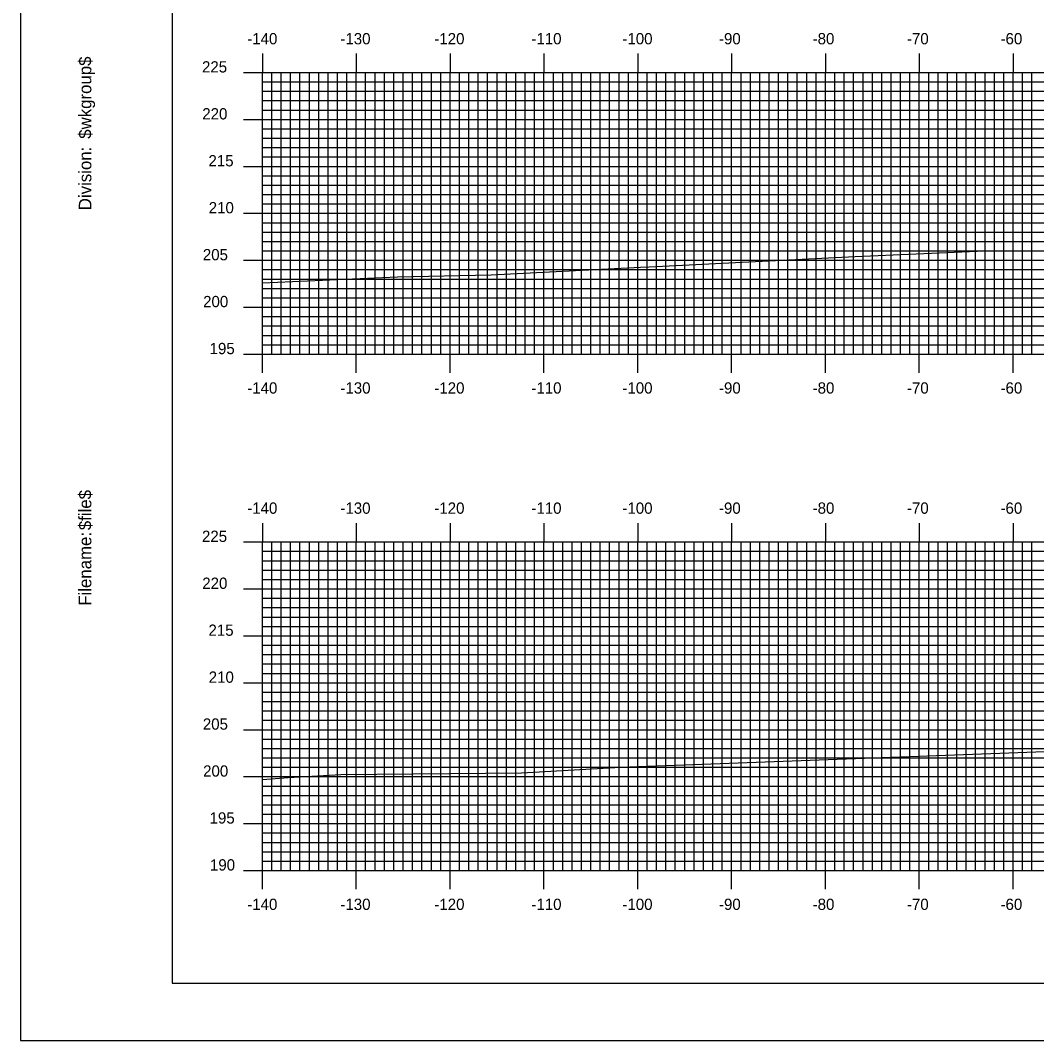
# Model space of a CAD drawing. Extents: x 853316 to 853659, y 364785 to 365005.
# Drawn here: x 853316 to 853424.3, y 364785.1 to 364893.8 of the extents above; entities that cross this region are included whole.
import ezdxf

# ---------------------------------------------------------------- set-up
doc = ezdxf.new("R2010")
doc.units = 0
for name, color, linetype in [('BORDER', 7, 'Continuous'), ('H_V ANNOTATION', 7, 'Continuous'), ('MAJOR', 7, 'Continuous'), ('MINOR', 7, 'Continuous'), ('PLOT BOUNDARY', 7, 'Continuous'), ('S_Roadway_Centerline', 7, 'Continuous')]:
    doc.layers.add(name, color=color, linetype=linetype)

msp = doc.modelspace()

# ---------------------------------------------------------------- linework, layer by layer
at = {"layer": 'BORDER'}
msp.add_lwpolyline([(853332.16, 364791.23), (853652.16, 364791.23), (853652.16, 365001.23), (853332.16, 365001.23)], close=True, dxfattribs=at)
at = {"layer": 'MAJOR'}
for p, q in [((853341.76, 364890.24), (853341.76, 364888.23)), ((853351.76, 364890.24), (853351.76, 364888.23)), ((853361.76, 364890.24), (853361.76, 364888.23)), ((853371.76, 364890.24), (853371.76, 364888.23)), ((853381.76, 364890.24), (853381.76, 364888.23)), ((853391.76, 364890.24), (853391.76, 364888.23)), ((853401.76, 364890.24), (853401.76, 364888.23)), ((853411.76, 364890.24), (853411.76, 364888.23)), ((853421.76, 364890.24), (853421.76, 364888.23)), ((853339.75, 364888.23), (853341.76, 364888.23)), ((853341.76, 364888.23), (853621.76, 364888.23)), ((853341.76, 364858.23), (853341.76, 364888.23)), ((853341.76, 364858.23), (853341.76, 364888.23)), ((853341.76, 364888.23), (853621.76, 364888.23)), ((853351.76, 364858.23), (853351.76, 364888.23)), ((853361.76, 364858.23), (853361.76, 364888.23)), ((853371.76, 364858.23), (853371.76, 364888.23)), ((853381.76, 364858.23), (853381.76, 364888.23)), ((853391.76, 364858.23), (853391.76, 364888.23)), ((853401.76, 364858.23), (853401.76, 364888.23)), ((853411.76, 364858.23), (853411.76, 364888.23)), ((853421.76, 364858.23), (853421.76, 364888.23)), ((853339.75, 364883.23), (853341.76, 364883.23)), ((853341.76, 364883.23), (853621.76, 364883.23)), ((853339.75, 364878.23), (853341.76, 364878.23)), ((853341.76, 364878.23), (853621.76, 364878.23)), ((853339.75, 364873.23), (853341.76, 364873.23)), ((853341.76, 364873.23), (853621.76, 364873.23)), ((853339.75, 364868.23), (853341.76, 364868.23)), ((853341.76, 364868.23), (853621.76, 364868.23)), ((853339.75, 364863.23), (853341.76, 364863.23)), ((853341.76, 364863.23), (853621.76, 364863.23)), ((853339.75, 364858.23), (853341.76, 364858.23)), ((853341.76, 364858.23), (853621.76, 364858.23)), ((853341.76, 364858.23), (853621.76, 364858.23)), ((853341.76, 364856.23), (853341.76, 364858.23)), ((853351.76, 364856.23), (853351.76, 364858.23)), ((853361.76, 364856.23), (853361.76, 364858.23)), ((853371.76, 364856.23), (853371.76, 364858.23)), ((853381.76, 364856.23), (853381.76, 364858.23)), ((853391.76, 364856.23), (853391.76, 364858.23)), ((853401.76, 364856.23), (853401.76, 364858.23)), ((853411.76, 364856.23), (853411.76, 364858.23)), ((853421.76, 364856.23), (853421.76, 364858.23)), ((853341.76, 364840.24), (853341.76, 364838.23)), ((853351.76, 364840.24), (853351.76, 364838.23)), ((853361.76, 364840.24), (853361.76, 364838.23)), ((853371.76, 364840.24), (853371.76, 364838.23)), ((853381.76, 364840.24), (853381.76, 364838.23)), ((853391.76, 364840.24), (853391.76, 364838.23)), ((853401.76, 364840.24), (853401.76, 364838.23)), ((853411.76, 364840.24), (853411.76, 364838.23)), ((853421.76, 364840.24), (853421.76, 364838.23)), ((853339.75, 364838.23), (853341.76, 364838.23)), ((853341.76, 364838.23), (853621.76, 364838.23)), ((853341.76, 364803.23), (853341.76, 364838.23)), ((853341.76, 364803.23), (853341.76, 364838.23)), ((853341.76, 364838.23), (853621.76, 364838.23)), ((853351.76, 364803.23), (853351.76, 364838.23)), ((853361.76, 364803.23), (853361.76, 364838.23)), ((853371.76, 364803.23), (853371.76, 364838.23)), ((853381.76, 364803.23), (853381.76, 364838.23)), ((853391.76, 364803.23), (853391.76, 364838.23)), ((853401.76, 364803.23), (853401.76, 364838.23)), ((853411.76, 364803.23), (853411.76, 364838.23)), ((853421.76, 364803.23), (853421.76, 364838.23)), ((853339.75, 364833.23), (853341.76, 364833.23)), ((853341.76, 364833.23), (853621.76, 364833.23)), ((853339.75, 364828.23), (853341.76, 364828.23)), ((853341.76, 364828.23), (853621.76, 364828.23)), ((853339.75, 364823.23), (853341.76, 364823.23)), ((853341.76, 364823.23), (853621.76, 364823.23)), ((853339.75, 364818.23), (853341.76, 364818.23)), ((853341.76, 364818.23), (853621.76, 364818.23)), ((853339.75, 364813.23), (853341.76, 364813.23)), ((853341.76, 364813.23), (853621.76, 364813.23)), ((853339.75, 364808.23), (853341.76, 364808.23)), ((853341.76, 364808.23), (853621.76, 364808.23)), ((853339.75, 364803.23), (853341.76, 364803.23)), ((853341.76, 364803.23), (853621.76, 364803.23)), ((853341.76, 364803.23), (853621.76, 364803.23)), ((853341.76, 364801.23), (853341.76, 364803.23)), ((853351.76, 364801.23), (853351.76, 364803.23)), ((853361.76, 364801.23), (853361.76, 364803.23)), ((853371.76, 364801.23), (853371.76, 364803.23)), ((853381.76, 364801.23), (853381.76, 364803.23)), ((853391.76, 364801.23), (853391.76, 364803.23)), ((853401.76, 364801.23), (853401.76, 364803.23)), ((853411.76, 364801.23), (853411.76, 364803.23)), ((853421.76, 364801.23), (853421.76, 364803.23))]:
    msp.add_line(p, q, dxfattribs=at)
at = {"layer": 'MINOR'}
for p, q in [((853342.76, 364858.23), (853342.76, 364888.23)), ((853343.76, 364858.23), (853343.76, 364888.23)), ((853344.76, 364858.23), (853344.76, 364888.23)), ((853345.76, 364858.23), (853345.76, 364888.23)), ((853346.76, 364858.23), (853346.76, 364888.23)), ((853347.76, 364858.23), (853347.76, 364888.23)), ((853348.76, 364858.23), (853348.76, 364888.23)), ((853349.76, 364858.23), (853349.76, 364888.23)), ((853350.76, 364858.23), (853350.76, 364888.23)), ((853352.76, 364858.23), (853352.76, 364888.23)), ((853353.76, 364858.23), (853353.76, 364888.23)), ((853354.76, 364858.23), (853354.76, 364888.23)), ((853355.76, 364858.23), (853355.76, 364888.23)), ((853356.76, 364858.23), (853356.76, 364888.23)), ((853357.76, 364858.23), (853357.76, 364888.23)), ((853358.76, 364858.23), (853358.76, 364888.23)), ((853359.76, 364858.23), (853359.76, 364888.23)), ((853360.76, 364858.23), (853360.76, 364888.23)), ((853362.76, 364858.23), (853362.76, 364888.23)), ((853363.76, 364858.23), (853363.76, 364888.23)), ((853364.76, 364858.23), (853364.76, 364888.23)), ((853365.76, 364858.23), (853365.76, 364888.23)), ((853366.76, 364858.23), (853366.76, 364888.23)), ((853367.76, 364858.23), (853367.76, 364888.23)), ((853368.76, 364858.23), (853368.76, 364888.23)), ((853369.76, 364858.23), (853369.76, 364888.23)), ((853370.76, 364858.23), (853370.76, 364888.23)), ((853372.76, 364858.23), (853372.76, 364888.23)), ((853373.76, 364858.23), (853373.76, 364888.23)), ((853374.76, 364858.23), (853374.76, 364888.23)), ((853375.76, 364858.23), (853375.76, 364888.23)), ((853376.76, 364858.23), (853376.76, 364888.23)), ((853377.76, 364858.23), (853377.76, 364888.23)), ((853378.76, 364858.23), (853378.76, 364888.23)), ((853379.76, 364858.23), (853379.76, 364888.23)), ((853380.76, 364858.23), (853380.76, 364888.23)), ((853382.76, 364858.23), (853382.76, 364888.23)), ((853383.76, 364858.23), (853383.76, 364888.23)), ((853384.76, 364858.23), (853384.76, 364888.23)), ((853385.76, 364858.23), (853385.76, 364888.23)), ((853386.76, 364858.23), (853386.76, 364888.23)), ((853387.76, 364858.23), (853387.76, 364888.23)), ((853388.76, 364858.23), (853388.76, 364888.23)), ((853389.76, 364858.23), (853389.76, 364888.23)), ((853390.76, 364858.23), (853390.76, 364888.23)), ((853392.76, 364858.23), (853392.76, 364888.23)), ((853393.76, 364858.23), (853393.76, 364888.23)), ((853394.76, 364858.23), (853394.76, 364888.23)), ((853395.76, 364858.23), (853395.76, 364888.23)), ((853396.76, 364858.23), (853396.76, 364888.23)), ((853397.76, 364858.23), (853397.76, 364888.23)), ((853398.76, 364858.23), (853398.76, 364888.23)), ((853399.76, 364858.23), (853399.76, 364888.23)), ((853400.76, 364858.23), (853400.76, 364888.23)), ((853402.76, 364858.23), (853402.76, 364888.23)), ((853403.76, 364858.23), (853403.76, 364888.23)), ((853404.76, 364858.23), (853404.76, 364888.23)), ((853405.76, 364858.23), (853405.76, 364888.23)), ((853406.76, 364858.23), (853406.76, 364888.23)), ((853407.76, 364858.23), (853407.76, 364888.23)), ((853408.76, 364858.23), (853408.76, 364888.23)), ((853409.76, 364858.23), (853409.76, 364888.23)), ((853410.76, 364858.23), (853410.76, 364888.23)), ((853412.76, 364858.23), (853412.76, 364888.23)), ((853413.76, 364858.23), (853413.76, 364888.23)), ((853414.76, 364858.23), (853414.76, 364888.23)), ((853415.76, 364858.23), (853415.76, 364888.23)), ((853416.76, 364858.23), (853416.76, 364888.23)), ((853417.76, 364858.23), (853417.76, 364888.23)), ((853418.76, 364858.23), (853418.76, 364888.23)), ((853419.76, 364858.23), (853419.76, 364888.23)), ((853420.76, 364858.23), (853420.76, 364888.23)), ((853422.76, 364858.23), (853422.76, 364888.23)), ((853423.76, 364858.23), (853423.76, 364888.23)), ((853341.76, 364887.23), (853621.76, 364887.23)), ((853341.76, 364887.23), (853343.76, 364887.23)), ((853341.76, 364886.23), (853621.76, 364886.23)), ((853341.76, 364886.23), (853343.76, 364886.23)), ((853341.76, 364885.23), (853621.76, 364885.23)), ((853341.76, 364885.23), (853343.76, 364885.23)), ((853341.76, 364884.23), (853621.76, 364884.23)), ((853341.76, 364884.23), (853343.76, 364884.23)), ((853341.76, 364882.23), (853621.76, 364882.23)), ((853341.76, 364882.23), (853343.76, 364882.23)), ((853341.76, 364881.23), (853621.76, 364881.23)), ((853341.76, 364881.23), (853343.76, 364881.23)), ((853341.76, 364880.23), (853621.76, 364880.23)), ((853341.76, 364880.23), (853343.76, 364880.23)), ((853341.76, 364879.23), (853621.76, 364879.23)), ((853341.76, 364879.23), (853343.76, 364879.23)), ((853341.76, 364877.23), (853621.76, 364877.23)), ((853341.76, 364877.23), (853343.76, 364877.23)), ((853341.76, 364876.23), (853621.76, 364876.23)), ((853341.76, 364876.23), (853343.76, 364876.23)), ((853341.76, 364875.23), (853621.76, 364875.23)), ((853341.76, 364875.23), (853343.76, 364875.23)), ((853341.76, 364874.23), (853621.76, 364874.23)), ((853341.76, 364874.23), (853343.76, 364874.23)), ((853341.76, 364872.23), (853621.76, 364872.23)), ((853341.76, 364872.23), (853343.76, 364872.23)), ((853341.76, 364871.23), (853621.76, 364871.23)), ((853341.76, 364871.23), (853343.76, 364871.23)), ((853341.76, 364870.23), (853621.76, 364870.23)), ((853341.76, 364870.23), (853343.76, 364870.23)), ((853341.76, 364869.23), (853621.76, 364869.23)), ((853341.76, 364869.23), (853343.76, 364869.23)), ((853341.76, 364867.23), (853621.76, 364867.23)), ((853341.76, 364867.23), (853343.76, 364867.23)), ((853341.76, 364866.23), (853621.76, 364866.23)), ((853341.76, 364866.23), (853343.76, 364866.23)), ((853341.76, 364865.23), (853621.76, 364865.23)), ((853341.76, 364865.23), (853343.76, 364865.23)), ((853341.76, 364864.23), (853621.76, 364864.23)), ((853341.76, 364864.23), (853343.76, 364864.23)), ((853341.76, 364862.23), (853621.76, 364862.23)), ((853341.76, 364862.23), (853343.76, 364862.23)), ((853341.76, 364861.23), (853621.76, 364861.23)), ((853341.76, 364861.23), (853343.76, 364861.23)), ((853341.76, 364860.23), (853621.76, 364860.23)), ((853341.76, 364860.23), (853343.76, 364860.23)), ((853341.76, 364859.23), (853621.76, 364859.23)), ((853341.76, 364859.23), (853343.76, 364859.23)), ((853342.76, 364803.23), (853342.76, 364838.23)), ((853343.76, 364803.23), (853343.76, 364838.23)), ((853344.76, 364803.23), (853344.76, 364838.23)), ((853345.76, 364803.23), (853345.76, 364838.23)), ((853346.76, 364803.23), (853346.76, 364838.23)), ((853347.76, 364803.23), (853347.76, 364838.23)), ((853348.76, 364803.23), (853348.76, 364838.23)), ((853349.76, 364803.23), (853349.76, 364838.23)), ((853350.76, 364803.23), (853350.76, 364838.23)), ((853352.76, 364803.23), (853352.76, 364838.23)), ((853353.76, 364803.23), (853353.76, 364838.23)), ((853354.76, 364803.23), (853354.76, 364838.23)), ((853355.76, 364803.23), (853355.76, 364838.23)), ((853356.76, 364803.23), (853356.76, 364838.23)), ((853357.76, 364803.23), (853357.76, 364838.23)), ((853358.76, 364803.23), (853358.76, 364838.23)), ((853359.76, 364803.23), (853359.76, 364838.23)), ((853360.76, 364803.23), (853360.76, 364838.23)), ((853362.76, 364803.23), (853362.76, 364838.23)), ((853363.76, 364803.23), (853363.76, 364838.23)), ((853364.76, 364803.23), (853364.76, 364838.23)), ((853365.76, 364803.23), (853365.76, 364838.23)), ((853366.76, 364803.23), (853366.76, 364838.23)), ((853367.76, 364803.23), (853367.76, 364838.23)), ((853368.76, 364803.23), (853368.76, 364838.23)), ((853369.76, 364803.23), (853369.76, 364838.23)), ((853370.76, 364803.23), (853370.76, 364838.23)), ((853372.76, 364803.23), (853372.76, 364838.23)), ((853373.76, 364803.23), (853373.76, 364838.23)), ((853374.76, 364803.23), (853374.76, 364838.23)), ((853375.76, 364803.23), (853375.76, 364838.23)), ((853376.76, 364803.23), (853376.76, 364838.23)), ((853377.76, 364803.23), (853377.76, 364838.23)), ((853378.76, 364803.23), (853378.76, 364838.23)), ((853379.76, 364803.23), (853379.76, 364838.23)), ((853380.76, 364803.23), (853380.76, 364838.23)), ((853382.76, 364803.23), (853382.76, 364838.23)), ((853383.76, 364803.23), (853383.76, 364838.23)), ((853384.76, 364803.23), (853384.76, 364838.23)), ((853385.76, 364803.23), (853385.76, 364838.23)), ((853386.76, 364803.23), (853386.76, 364838.23)), ((853387.76, 364803.23), (853387.76, 364838.23)), ((853388.76, 364803.23), (853388.76, 364838.23)), ((853389.76, 364803.23), (853389.76, 364838.23)), ((853390.76, 364803.23), (853390.76, 364838.23)), ((853392.76, 364803.23), (853392.76, 364838.23)), ((853393.76, 364803.23), (853393.76, 364838.23)), ((853394.76, 364803.23), (853394.76, 364838.23)), ((853395.76, 364803.23), (853395.76, 364838.23)), ((853396.76, 364803.23), (853396.76, 364838.23)), ((853397.76, 364803.23), (853397.76, 364838.23)), ((853398.76, 364803.23), (853398.76, 364838.23)), ((853399.76, 364803.23), (853399.76, 364838.23)), ((853400.76, 364803.23), (853400.76, 364838.23)), ((853402.76, 364803.23), (853402.76, 364838.23)), ((853403.76, 364803.23), (853403.76, 364838.23)), ((853404.76, 364803.23), (853404.76, 364838.23)), ((853405.76, 364803.23), (853405.76, 364838.23)), ((853406.76, 364803.23), (853406.76, 364838.23)), ((853407.76, 364803.23), (853407.76, 364838.23)), ((853408.76, 364803.23), (853408.76, 364838.23)), ((853409.76, 364803.23), (853409.76, 364838.23)), ((853410.76, 364803.23), (853410.76, 364838.23)), ((853412.76, 364803.23), (853412.76, 364838.23)), ((853413.76, 364803.23), (853413.76, 364838.23)), ((853414.76, 364803.23), (853414.76, 364838.23)), ((853415.76, 364803.23), (853415.76, 364838.23)), ((853416.76, 364803.23), (853416.76, 364838.23)), ((853417.76, 364803.23), (853417.76, 364838.23)), ((853418.76, 364803.23), (853418.76, 364838.23)), ((853419.76, 364803.23), (853419.76, 364838.23)), ((853420.76, 364803.23), (853420.76, 364838.23)), ((853422.76, 364803.23), (853422.76, 364838.23)), ((853423.76, 364803.23), (853423.76, 364838.23)), ((853341.76, 364837.23), (853621.76, 364837.23)), ((853341.76, 364837.23), (853343.76, 364837.23)), ((853341.76, 364836.23), (853621.76, 364836.23)), ((853341.76, 364836.23), (853343.76, 364836.23)), ((853341.76, 364835.23), (853621.76, 364835.23)), ((853341.76, 364835.23), (853343.76, 364835.23)), ((853341.76, 364834.23), (853621.76, 364834.23)), ((853341.76, 364834.23), (853343.76, 364834.23)), ((853341.76, 364832.23), (853621.76, 364832.23)), ((853341.76, 364832.23), (853343.76, 364832.23)), ((853341.76, 364831.23), (853621.76, 364831.23)), ((853341.76, 364831.23), (853343.76, 364831.23)), ((853341.76, 364830.23), (853621.76, 364830.23)), ((853341.76, 364830.23), (853343.76, 364830.23)), ((853341.76, 364829.23), (853621.76, 364829.23)), ((853341.76, 364829.23), (853343.76, 364829.23)), ((853341.76, 364827.23), (853621.76, 364827.23)), ((853341.76, 364827.23), (853343.76, 364827.23)), ((853341.76, 364826.23), (853621.76, 364826.23)), ((853341.76, 364826.23), (853343.76, 364826.23)), ((853341.76, 364825.23), (853621.76, 364825.23)), ((853341.76, 364825.23), (853343.76, 364825.23)), ((853341.76, 364824.23), (853621.76, 364824.23)), ((853341.76, 364824.23), (853343.76, 364824.23)), ((853341.76, 364822.23), (853621.76, 364822.23)), ((853341.76, 364822.23), (853343.76, 364822.23)), ((853341.76, 364821.23), (853621.76, 364821.23)), ((853341.76, 364821.23), (853343.76, 364821.23)), ((853341.76, 364820.23), (853621.76, 364820.23)), ((853341.76, 364820.23), (853343.76, 364820.23)), ((853341.76, 364819.23), (853621.76, 364819.23)), ((853341.76, 364819.23), (853343.76, 364819.23)), ((853341.76, 364817.23), (853621.76, 364817.23)), ((853341.76, 364817.23), (853343.76, 364817.23)), ((853341.76, 364816.23), (853621.76, 364816.23)), ((853341.76, 364816.23), (853343.76, 364816.23)), ((853341.76, 364815.23), (853621.76, 364815.23)), ((853341.76, 364815.23), (853343.76, 364815.23)), ((853341.76, 364814.23), (853621.76, 364814.23)), ((853341.76, 364814.23), (853343.76, 364814.23)), ((853341.76, 364812.23), (853621.76, 364812.23)), ((853341.76, 364812.23), (853343.76, 364812.23)), ((853341.76, 364811.23), (853621.76, 364811.23)), ((853341.76, 364811.23), (853343.76, 364811.23)), ((853341.76, 364810.23), (853621.76, 364810.23)), ((853341.76, 364810.23), (853343.76, 364810.23)), ((853341.76, 364809.23), (853621.76, 364809.23)), ((853341.76, 364809.23), (853343.76, 364809.23)), ((853341.76, 364807.23), (853621.76, 364807.23)), ((853341.76, 364807.23), (853343.76, 364807.23)), ((853341.76, 364806.23), (853621.76, 364806.23)), ((853341.76, 364806.23), (853343.76, 364806.23)), ((853341.76, 364805.23), (853621.76, 364805.23)), ((853341.76, 364805.23), (853343.76, 364805.23)), ((853341.76, 364804.23), (853621.76, 364804.23)), ((853341.76, 364804.23), (853343.76, 364804.23))]:
    msp.add_line(p, q, dxfattribs=at)
at = {"layer": 'PLOT BOUNDARY'}
msp.add_lwpolyline([(853315.97, 364785.11), (853655.97, 364785.11), (853655.97, 365005.11), (853315.97, 365005.11)], close=True, dxfattribs=at)
at = {"layer": 'S_Roadway_Centerline'}
for points in [[(853341.76, 364865.84), (853356.16, 364866.46), (853366.14, 364866.68), (853382.04, 364867.48), (853382.97, 364867.53), (853404.92, 364868.62), (853417.92, 364869.21), (853430.2, 364869.26), (853438.03, 364869.75), (853465.49, 364870.45), (853470.73, 364870.78), (853484.26, 364871.97), (853500.06, 364872.67), (853501.84, 364872.73), (853506.29, 364872.95), (853515.89, 364873.45), (853518.86, 364873.58), (853529.02, 364874.09), (853536.1, 364874.57)], [(853341.76, 364812.92), (853344.5, 364813.14), (853347.01, 364813.28), (853350.12, 364813.44), (853369.35, 364813.65), (853379.97, 364814.25), (853427.05, 364815.97), (853430, 364816.11), (853430.31, 364816.12), (853437.12, 364816.56), (853456.88, 364817.9), (853464.71, 364818.39), (853478.31, 364819.19), (853505.33, 364821.12), (853514.36, 364821.74), (853514.96, 364821.79), (853516.88, 364822.05), (853540.71, 364825.86)]]:
    msp.add_lwpolyline(points, dxfattribs=at)

# ---------------------------------------------------------------- texts
at = {"layer": 'BORDER'}
for s, p in [('$wkgroup$', (853323.53, 364881.17)), ('Division:', (853323.53, 364873.56)), ('$file$', (853323.53, 364839.48)), ('Filename:', (853323.53, 364831.43))]:
    msp.add_text(s, height=1.339, rotation=90, dxfattribs=at).set_placement(p)
at = {"layer": 'H_V ANNOTATION'}
for s, p in [('-140', (853340.14, 364891.23)), ('-130', (853350.07, 364891.23)), ('-120', (853360.08, 364891.23)), ('-110', (853370.42, 364891.23)), ('-100', (853380.12, 364891.23)), ('-90', (853390.41, 364891.23)), ('-80', (853400.39, 364891.23)), ('-70', (853410.44, 364891.23)), ('-60', (853420.41, 364891.23)), ('225', (853335.32, 364888.23)), ('220', (853335.35, 364883.23)), ('215', (853336.01, 364878.23)), ('210', (853336.04, 364873.23)), ('205', (853335.41, 364868.23)), ('200', (853335.44, 364863.23)), ('195', (853336.13, 364858.23)), ('-140', (853340.14, 364854.03)), ('-130', (853350.07, 364854.03)), ('-120', (853360.08, 364854.03)), ('-110', (853370.42, 364854.03)), ('-100', (853380.12, 364854.03)), ('-90', (853390.41, 364854.03)), ('-80', (853400.39, 364854.03)), ('-70', (853410.44, 364854.03)), ('-60', (853420.41, 364854.03)), ('-140', (853340.14, 364841.23)), ('-130', (853350.07, 364841.23)), ('-120', (853360.08, 364841.23)), ('-110', (853370.42, 364841.23)), ('-100', (853380.12, 364841.23)), ('-90', (853390.41, 364841.23)), ('-80', (853400.39, 364841.23)), ('-70', (853410.44, 364841.23)), ('-60', (853420.41, 364841.23)), ('225', (853335.32, 364838.23)), ('220', (853335.35, 364833.23)), ('215', (853336.01, 364828.23)), ('210', (853336.04, 364823.23)), ('205', (853335.41, 364818.23)), ('200', (853335.44, 364813.23)), ('195', (853336.13, 364808.23)), ('190', (853336.17, 364803.23)), ('-140', (853340.14, 364799.03)), ('-130', (853350.07, 364799.03)), ('-120', (853360.08, 364799.03)), ('-110', (853370.42, 364799.03)), ('-100', (853380.12, 364799.03)), ('-90', (853390.41, 364799.03)), ('-80', (853400.39, 364799.03)), ('-70', (853410.44, 364799.03)), ('-60', (853420.41, 364799.03))]:
    msp.add_text(s, height=1.2, dxfattribs=at).set_placement(p)
at = {"layer": 'MAJOR'}
for p in [(853341.75, 364858.23), (853341.75, 364803.23)]:
    msp.add_text('-', height=0.012, dxfattribs=at).set_placement(p)

doc.saveas('drawing.dxf')
